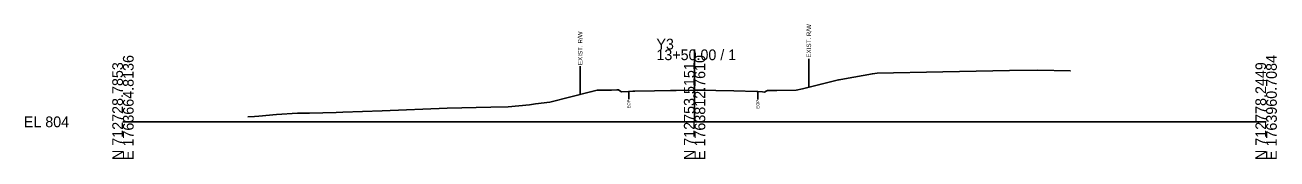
# Model space of a CAD drawing. Extents: x -26 to 2903, y -10 to 5022.
# Drawn here: x -25.7 to 302.8, y 3490.3 to 3525.3 of the extents above; entities that cross this region are included whole.
import ezdxf

# ---------------------------------------------------------------- set-up
doc = ezdxf.new("R2010")
doc.units = 0
for name, color, linetype in [('Default', 7, 'Continuous'), ('Exist Cross Section Cell', 7, 'Continuous'), ('Exist XS Ground Line', 7, 'Continuous'), ('Old_Level_10', 7, 'Continuous')]:
    doc.layers.add(name, color=color, linetype=linetype)

msp = doc.modelspace()

# ---------------------------------------------------------------- linework, layer by layer
at = {"layer": 'Exist Cross Section Cell'}
for p, q in [((150, 3500), (150, 3518.94)), ((0, 3500), (150, 3500)), ((150, 3500), (300, 3500))]:
    msp.add_line(p, q, dxfattribs=at)
at = {"layer": 'Exist XS Ground Line'}
msp.add_lwpolyline([(32.8, 3501.31), (34.54, 3501.39), (35.67, 3501.52), (40.31, 3501.96), (45.81, 3502.27), (48.99, 3502.29), (55.95, 3502.45), (57.68, 3502.54), (68.02, 3502.92), (85.09, 3503.57), (96.51, 3503.81), (101.11, 3503.94), (106.65, 3504.45), (108.29, 3504.7), (112.02, 3505.16), (123.06, 3507.93), (124.45, 3508.28), (125.01, 3508.28), (128.18, 3508.33), (129.65, 3508.34), (130.14, 3508.35), (130.17, 3508.33), (130.85, 3507.88), (132.66, 3507.98), (132.73, 3507.98), (133.82, 3508.01), (134.31, 3508.02), (139.5, 3508.1), (143.66, 3508.18), (145.14, 3508.22), (150, 3508.29), (150.04, 3508.29), (152.54, 3508.27), (155.59, 3508.2), (160.28, 3508.08), (166.38, 3507.93), (166.62, 3507.92), (167.84, 3507.81), (168.38, 3507.77), (168.79, 3508), (169.18, 3508.23), (169.18, 3508.23), (170.83, 3508.18), (171.57, 3508.2), (176.68, 3508.29), (178.29, 3508.67), (183.2, 3509.9), (187.76, 3510.98), (187.98, 3511.02), (189.33, 3511.26), (196.67, 3512.6), (197.89, 3512.75), (215.16, 3513.1), (232.65, 3513.43), (240.1, 3513.56), (248.59, 3513.34), (248.62, 3513.33)], dxfattribs=at)
at = {"layer": 'Old_Level_10'}
for p, q in [((180, 3516.5), (180, 3509.1)), ((120, 3514.56), (120, 3507.16)), ((132.73, 3507.98), (132.73, 3505.93)), ((166.62, 3507.92), (166.62, 3505.87))]:
    msp.add_line(p, q, dxfattribs=at)

# ---------------------------------------------------------------- texts
at = {"layer": 'Default'}
msp.add_text('-', height=0.0001, dxfattribs=at).set_placement((0, 3500))
at = {"layer": 'Exist Cross Section Cell'}
for s, p in [('Y3', (140, 3518.94)), ('13+50.00 / 1', (140, 3516.14)), ('EL 804', (-26, 3498.6))]:
    msp.add_text(s, height=2.8, dxfattribs=at).set_placement(p)
for s, p in [('N 712728.7853', (0, 3490)), ('E 1763664.8136', (2.8, 3490)), ('N 712753.5151', (150, 3490)), ('E 1763812.7610', (152.8, 3490)), ('N 712778.2449', (300, 3490)), ('E 1763960.7084', (302.8, 3490))]:
    msp.add_text(s, height=2.8, rotation=90, dxfattribs=at).set_placement(p)
at = {"layer": 'Old_Level_10'}
for s, height, p in [('EXIST. R/W', 1.181, (180.59, 3516.8)), ('EXIST. R/W', 1.181, (120.59, 3514.86)), ('EOP', 0.787, (133.13, 3503.53)), ('EOP', 0.787, (167.01, 3503.47))]:
    msp.add_text(s, height=height, rotation=90, dxfattribs=at).set_placement(p)

doc.saveas('drawing.dxf')
